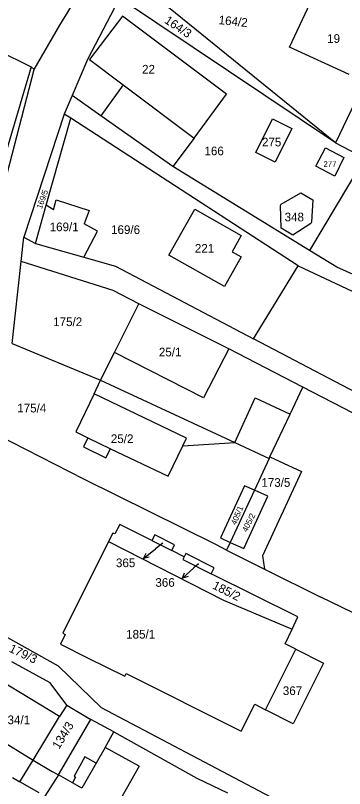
# Model space of a CAD drawing. Extents: x -593358 to -590116, y -1072518 to -1068420.
# Drawn here: x -591697.7 to -591633.2, y -1070880.4 to -1070728.7 of the extents above; entities that cross this region are included whole.
import ezdxf

# ---------------------------------------------------------------- set-up
doc = ezdxf.new("R2010")
doc.units = 0
for name, color, linetype in [('Parcela KN', 7, 'Continuous'), ('Parcela ZE', 7, 'Continuous'), ('Parcelní číslo', 7, 'Continuous'), ('Parcelní číslo_stavební', 7, 'Continuous'), ('stavby - vnitřní kresba', 7, 'Continuous'), ('Vrstva 16', 7, 'Continuous')]:
    doc.layers.add(name, color=color, linetype=linetype)

msp = doc.modelspace()

# ---------------------------------------------------------------- linework, layer by layer
at = {"layer": 'Parcela KN'}
for p, q in [((-591688.96, -1070730.57), (-591682.35, -1070719.59)), ((-591634.98, -1070753.71), (-591674.03, -1070721.94)), ((-591643.97, -1070734.91), (-591639.24, -1070724.7)), ((-591634.98, -1070753.71), (-591676.93, -1070725.51)), ((-591678.3, -1070727.2), (-591683.56, -1070737.32)), ((-591676.72, -1070728.84), (-591683.16, -1070737.34)), ((-591656.35, -1070744.13), (-591676.72, -1070728.84)), ((-591623.26, -1070729.02), (-591634.98, -1070753.71)), ((-591694.05, -1070739.29), (-591688.96, -1070730.57)), ((-591702.24, -1070734.99), (-591694.58, -1070738.76)), ((-591632.28, -1070740.28), (-591643.97, -1070734.91)), ((-591683.56, -1070737.32), (-591686.58, -1070744.4)), ((-591694.58, -1070738.76), (-591700.63, -1070759.16)), ((-591694.05, -1070739.29), (-591694.58, -1070738.76)), ((-591683.16, -1070737.34), (-591676.56, -1070742.3)), ((-591701.3, -1070767.34), (-591694.05, -1070739.29)), ((-591676.56, -1070742.3), (-591680.97, -1070748.36)), ((-591686.58, -1070744.4), (-591688.15, -1070748.09)), ((-591680.97, -1070748.36), (-591686.58, -1070744.4)), ((-591662.66, -1070752.74), (-591656.35, -1070744.13)), ((-591688.15, -1070748.09), (-591696.05, -1070772.19)), ((-591691.64, -1070765.94), (-591686.85, -1070748.82)), ((-591686.85, -1070748.82), (-591688.15, -1070748.09)), ((-591642.27, -1070777.79), (-591686.85, -1070748.82)), ((-591666.82, -1070758.36), (-591680.97, -1070748.36)), ((-591650.6, -1070755.57), (-591647.33, -1070748.96)), ((-591647.33, -1070748.96), (-591643.51, -1070750.85)), ((-591643.51, -1070750.85), (-591646.78, -1070757.46)), ((-591662.66, -1070752.74), (-591666.82, -1070758.36)), ((-591634.98, -1070753.71), (-591629.3, -1070756.68)), ((-591638.82, -1070758.24), (-591636.94, -1070754.65)), ((-591636.94, -1070754.65), (-591633.32, -1070756.58)), ((-591646.78, -1070757.46), (-591650.6, -1070755.57)), ((-591629.3, -1070756.68), (-591640.1, -1070774.78)), ((-591633.32, -1070756.58), (-591635.11, -1070760.22)), ((-591640.1, -1070774.78), (-591666.82, -1070758.36)), ((-591635.11, -1070760.22), (-591638.82, -1070758.24)), ((-591645.63, -1070765.72), (-591641.76, -1070763.49)), ((-591641.76, -1070763.49), (-591639.44, -1070764.86)), ((-591693.74, -1070773.46), (-591691.64, -1070765.94)), ((-591645.78, -1070765.99), (-591645.63, -1070765.72)), ((-591645.63, -1070770.46), (-591645.78, -1070765.99)), ((-591639.44, -1070764.86), (-591639.66, -1070769.26)), ((-591667.62, -1070775.7), (-591662.51, -1070766.67)), ((-591662.51, -1070766.67), (-591653.49, -1070771.89)), ((-591643.33, -1070771.81), (-591645.63, -1070770.46)), ((-591639.81, -1070769.54), (-591643.33, -1070771.81)), ((-591639.66, -1070769.26), (-591639.81, -1070769.54)), ((-591696.56, -1070776.94), (-591696.05, -1070772.19)), ((-591696.05, -1070772.19), (-591693.74, -1070773.46)), ((-591653.49, -1070771.89), (-591655.23, -1070775.08)), ((-591693.74, -1070773.46), (-591684.32, -1070776.12)), ((-591655.23, -1070775.08), (-591653.46, -1070776.05)), ((-591634.73, -1070778.08), (-591640.1, -1070774.78)), ((-591684.32, -1070776.12), (-591678.08, -1070777.88)), ((-591656.74, -1070781.86), (-591667.62, -1070775.7)), ((-591653.46, -1070776.05), (-591656.74, -1070781.86)), ((-591698.3, -1070793.09), (-591696.56, -1070776.94)), ((-591678.53, -1070782.69), (-591696.56, -1070776.94)), ((-591678.08, -1070777.88), (-591651.06, -1070792.13)), ((-591651.06, -1070792.13), (-591642.27, -1070777.79)), ((-591642.27, -1070777.79), (-591603.41, -1070796.18)), ((-591603.24, -1070792.27), (-591634.73, -1070778.08)), ((-591673.52, -1070785.29), (-591678.53, -1070782.69)), ((-591678.31, -1070794.83), (-591673.52, -1070785.29)), ((-591655.88, -1070794.11), (-591673.52, -1070785.29)), ((-591698.3, -1070793.09), (-591681.05, -1070800.25)), ((-591614.04, -1070811.57), (-591651.06, -1070792.13)), ((-591681.05, -1070800.25), (-591678.31, -1070794.83)), ((-591641.37, -1070801.65), (-591655.88, -1070794.11)), ((-591682.29, -1070802.96), (-591681.05, -1070800.25)), ((-591681.05, -1070800.25), (-591654.73, -1070812.47)), ((-591643.87, -1070806.94), (-591641.37, -1070801.65)), ((-591584.73, -1070831.08), (-591641.37, -1070801.65)), ((-591682.29, -1070802.96), (-591685.86, -1070810.4)), ((-591647.83, -1070815.32), (-591643.87, -1070806.94)), ((-591684.3, -1070819.65), (-591704.86, -1070809.18)), ((-591685.86, -1070810.4), (-591683.53, -1070811.56)), ((-591683.53, -1070811.56), (-591684.36, -1070813.35)), ((-591667.77, -1070819.07), (-591664.91, -1070813.12)), ((-591664.91, -1070813.12), (-591654.73, -1070812.47)), ((-591654.73, -1070812.47), (-591647.96, -1070815.62)), ((-591684.36, -1070813.35), (-591679.96, -1070815.46)), ((-591679.96, -1070815.46), (-591679.06, -1070813.7)), ((-591679.06, -1070813.7), (-591667.77, -1070819.07)), ((-591647.96, -1070815.62), (-591650.86, -1070821.86)), ((-591647.96, -1070815.62), (-591647.83, -1070815.32)), ((-591647.83, -1070815.32), (-591645.19, -1070816.52)), ((-591645.19, -1070816.52), (-591641.65, -1070818.17)), ((-591641.65, -1070818.17), (-591649.27, -1070834.74)), ((-591658.41, -1070832.5), (-591684.3, -1070819.65)), ((-591652.8, -1070820.99), (-591657.49, -1070831.22)), ((-591650.86, -1070821.86), (-591655.6, -1070832.09)), ((-591650.86, -1070821.86), (-591652.8, -1070820.99)), ((-591648.23, -1070823.03), (-591650.86, -1070821.86)), ((-591652.93, -1070833.3), (-591648.23, -1070823.03)), ((-591677.25, -1070828.56), (-591678.24, -1070830.43)), ((-591670.94, -1070831.73), (-591677.25, -1070828.56)), ((-591678.6, -1070830.24), (-591679.43, -1070831.91)), ((-591678.24, -1070830.43), (-591678.6, -1070830.24)), ((-591670.38, -1070830.61), (-591670.94, -1070831.73)), ((-591666.5, -1070832.55), (-591670.38, -1070830.61)), ((-591657.49, -1070831.22), (-591655.6, -1070832.09)), ((-591679.43, -1070831.91), (-591688.41, -1070849.92)), ((-591679.43, -1070831.91), (-591656.95, -1070843.42)), ((-591670.94, -1070831.73), (-591667.06, -1070833.67)), ((-591667.06, -1070833.67), (-591666.5, -1070832.55)), ((-591656.31, -1070833.63), (-591658.41, -1070832.5)), ((-591655.6, -1070832.09), (-591656.31, -1070833.63)), ((-591655.6, -1070832.09), (-591652.93, -1070833.3)), ((-591664.61, -1070834.9), (-591667.06, -1070833.67)), ((-591664.3, -1070834.29), (-591664.61, -1070834.9)), ((-591658.78, -1070837.06), (-591664.3, -1070834.29)), ((-591656.31, -1070833.63), (-591648.92, -1070837.33)), ((-591664.61, -1070834.9), (-591664.88, -1070835.43)), ((-591664.88, -1070835.43), (-591659.36, -1070838.22)), ((-591649.27, -1070834.74), (-591648.92, -1070837.33)), ((-591659.36, -1070838.22), (-591658.78, -1070837.06)), ((-591648.92, -1070837.33), (-591637.83, -1070842.8)), ((-591642.37, -1070846.72), (-591659.36, -1070838.22)), ((-591656.95, -1070843.42), (-591643.5, -1070849.11)), ((-591609.19, -1070856.91), (-591637.83, -1070842.8)), ((-591643.5, -1070849.11), (-591642.37, -1070846.72)), ((-591644.86, -1070851.98), (-591643.5, -1070849.11)), ((-591689.25, -1070856.37), (-591700.88, -1070849.92)), ((-591687.96, -1070850.14), (-591688.89, -1070852.03)), ((-591688.41, -1070849.92), (-591687.96, -1070850.14)), ((-591688.89, -1070852.03), (-591683.42, -1070854.77)), ((-591642.76, -1070853.03), (-591644.86, -1070851.98)), ((-591648.68, -1070864.91), (-591642.76, -1070853.03)), ((-591642.76, -1070853.03), (-591637.31, -1070855.77)), ((-591690.91, -1070859.62), (-591698.38, -1070855.49)), ((-591683.42, -1070854.77), (-591676.25, -1070858.35)), ((-591680.84, -1070864.53), (-591689.25, -1070856.37)), ((-591637.31, -1070855.77), (-591643.26, -1070867.68)), ((-591676.25, -1070858.35), (-591675.97, -1070857.82)), ((-591675.97, -1070857.82), (-591653.47, -1070869.12)), ((-591687.6, -1070863.99), (-591690.91, -1070859.62)), ((-591687.6, -1070863.99), (-591689.07, -1070866.25)), ((-591687.6, -1070863.99), (-591682.93, -1070866.84)), ((-591627.12, -1070892.85), (-591680.84, -1070864.53)), ((-591653.47, -1070869.12), (-591650.78, -1070863.84)), ((-591650.78, -1070863.84), (-591648.68, -1070864.91)), ((-591694.23, -1070874.79), (-591689.07, -1070866.25)), ((-591643.26, -1070867.68), (-591648.68, -1070864.91)), ((-591689.26, -1070877.67), (-591682.93, -1070866.84)), ((-591678.42, -1070869.23), (-591682.93, -1070866.84)), ((-591680.11, -1070872.33), (-591678.42, -1070869.23)), ((-591678.42, -1070869.23), (-591662.13, -1070878.34)), ((-591673.47, -1070875.99), (-591680.11, -1070872.33)), ((-591696.8, -1070879.05), (-591694.23, -1070874.79)), ((-591673.47, -1070875.99), (-591680.18, -1070887.91)), ((-591698.28, -1070878.19), (-591696.8, -1070879.05)), ((-591689.26, -1070877.67), (-591691.91, -1070881.87)), ((-591662.13, -1070878.34), (-591656.14, -1070881.22)), ((-591693.01, -1070881.24), (-591696.8, -1070879.05))]:
    msp.add_line(p, q, dxfattribs=at)
at = {"layer": 'Parcela ZE'}
for p, q in [((-591690.2, -1070766.85), (-591691.64, -1070765.94)), ((-591690.2, -1070766.85), (-591689.7, -1070764.9)), ((-591689.7, -1070764.9), (-591683.22, -1070766.97)), ((-591683.22, -1070766.97), (-591684.23, -1070769.56)), ((-591681.6, -1070771), (-591684.23, -1070769.56)), ((-591684.32, -1070776.12), (-591681.6, -1070771))]:
    msp.add_line(p, q, dxfattribs=at)
at = {"layer": 'stavby - vnitřní kresba'}
for p, q in [((-591676.56, -1070742.3), (-591662.66, -1070752.74)), ((-591660.82, -1070803.75), (-591678.31, -1070794.83)), ((-591655.88, -1070794.11), (-591660.82, -1070803.75)), ((-591664.2, -1070811.65), (-591682.29, -1070802.96)), ((-591654.73, -1070812.47), (-591650.72, -1070803.75)), ((-591650.72, -1070803.75), (-591643.87, -1070806.94)), ((-591683.53, -1070811.56), (-591679.06, -1070813.7)), ((-591664.91, -1070813.12), (-591664.2, -1070811.65)), ((-591689.07, -1070866.25), (-591700.75, -1070859.19)), ((-591705.74, -1070867.75), (-591694.23, -1070874.79)), ((-591680.11, -1070872.33), (-591681.89, -1070875.43)), ((-591694.23, -1070874.79), (-591690.49, -1070877.05)), ((-591684.11, -1070874.16), (-591686.2, -1070877.95)), ((-591681.89, -1070875.43), (-591684.11, -1070874.16)), ((-591681.89, -1070875.43), (-591684.67, -1070880.32)), ((-591690.49, -1070877.05), (-591689.26, -1070877.67)), ((-591686.53, -1070879.25), (-591689.26, -1070877.67)), ((-591685.9, -1070878.12), (-591686.53, -1070879.25)), ((-591686.2, -1070877.95), (-591685.9, -1070878.12)), ((-591684.67, -1070880.32), (-591686.53, -1070879.25))]:
    msp.add_line(p, q, dxfattribs=at)
at = {"layer": 'Vrstva 16'}
for p, q in [((-591668.83, -1070832.25), (-591670.23, -1070833.37)), ((-591672.575, -1070835.24), (-591670.23, -1070833.37)), ((-591664.945, -1070839.092), (-591662.72, -1070837.08)), ((-591661.83, -1070836.27), (-591662.72, -1070837.08))]:
    msp.add_line(p, q, dxfattribs=at)
for points in [[(-591671.482, -1070835.008), (-591672.575, -1070835.24), (-591672.105, -1070834.226)], [(-591663.868, -1070838.792), (-591664.945, -1070839.092), (-591664.539, -1070838.051)]]:
    msp.add_lwpolyline(points, dxfattribs=at)

# ---------------------------------------------------------------- texts
at = {"layer": 'Parcelní číslo'}
for s, height, rotation, p in [('164/3', 1.7, 326.29946, (-591668.639, -1070730.04)), ('164/2', 1.7, 354.03062, (-591657.942, -1070730.381)), ('169/5', 1.14, 70.76029, (-591692.512, -1070766.743))]:
    msp.add_text(s, height=height, rotation=rotation, dxfattribs=at).set_placement(p)
for s, p in [('166', (-591660.656, -1070756.13)), ('169/1', (-591690.987, -1070771.03)), ('169/6', (-591678.955, -1070771.57)), ('175/2', (-591690.296, -1070789.65)), ('175/4', (-591697.332, -1070806.58)), ('173/5', (-591649.509, -1070821.18))]:
    msp.add_text(s, height=1.7, dxfattribs=at).set_placement(p)
at = {"layer": 'Parcelní číslo_stavební'}
for s, height, p in [('19', 1.7, (-591636.617, -1070734.07)), ('22', 1.7, (-591672.882, -1070740.1)), ('275', 1.7, (-591649.385, -1070754.39)), ('277', 1.14, (-591637.336, -1070758.43)), ('348', 1.7, (-591644.951, -1070769.09)), ('221', 1.7, (-591662.533, -1070775.24)), ('25/1', 1.7, (-591669.586, -1070795.59)), ('25/2', 1.7, (-591678.998, -1070812.59)), ('365', 0.1, (-591669.023, -1070832.25)), ('366', 0.1, (-591661.95, -1070836.27)), ('185/1', 1.7, (-591676.001, -1070850.95)), ('367', 1.7, (-591645.301, -1070862.03)), ('134/1', 1.7, (-591700.504, -1070867.75))]:
    msp.add_text(s, height=height, dxfattribs=at).set_placement(p)
for s, height, rotation, p in [('405/1', 1.14, 67.43713, (-591654.473, -1070828.746)), ('405/2', 1.14, 63.99939, (-591652.323, -1070830.158)), ('185/2', 1.7, 333.46144, (-591659.242, -1070841.076)), ('134/3', 1.7, 58.3844, (-591689.159, -1070872.795))]:
    msp.add_text(s, height=height, rotation=rotation, dxfattribs=at).set_placement(p)
at = {"layer": 'Vrstva 16'}
for s, p in [('365', (-591677.994, -1070836.94)), ('366', (-591670.27, -1070840.79))]:
    msp.add_text(s, height=1.7, dxfattribs=at).set_placement(p)
msp.add_text('179/3', height=1.7, rotation=334.49276, dxfattribs=at).set_placement((-591699.086, -1070853.459))

doc.saveas('drawing.dxf')
